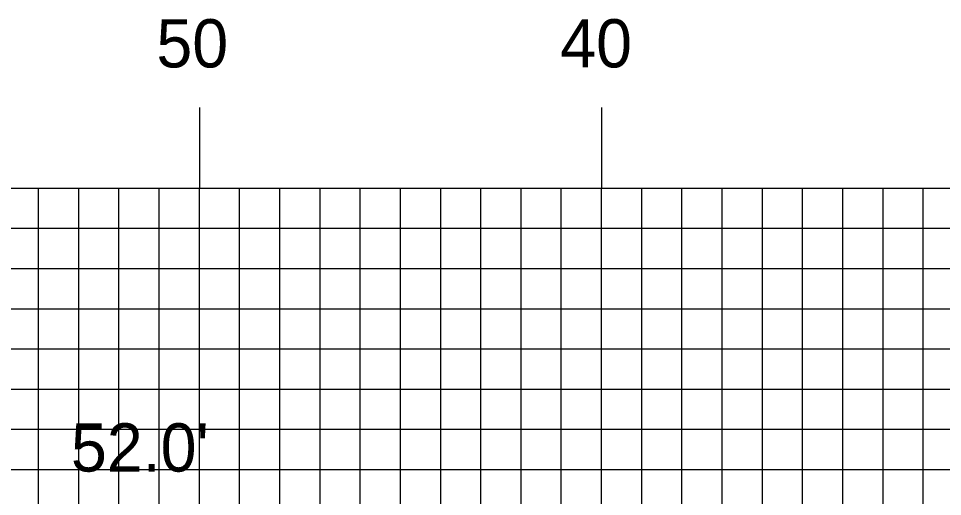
# Model space of a CAD drawing. Extents: x 1771629 to 1771972, y 442591 to 442811.
# Drawn here: x 1771740.08 to 1771763.06, y 442625.99 to 442637.88 of the extents above; entities that cross this region are included whole.
import ezdxf

# ---------------------------------------------------------------- set-up
doc = ezdxf.new("R2010")
doc.units = 0
for name, color, linetype in [('D_Text_Standard', 7, 'Continuous'), ('H_V ANNOTATION', 7, 'Continuous'), ('MAJOR', 7, 'Continuous'), ('MINOR', 7, 'Continuous')]:
    doc.layers.add(name, color=color, linetype=linetype)

msp = doc.modelspace()

# ---------------------------------------------------------------- linework, layer by layer
at = {"layer": 'MAJOR'}
for p, q in [((1771744.58, 442635.669), (1771744.58, 442633.665)), ((1771754.58, 442635.669), (1771754.58, 442633.665)), ((1771654.58, 442633.665), (1771934.58, 442633.665)), ((1771654.58, 442633.665), (1771934.58, 442633.665)), ((1771744.58, 442608.665), (1771744.58, 442633.665)), ((1771754.58, 442608.665), (1771754.58, 442633.665)), ((1771654.58, 442628.665), (1771934.58, 442628.665))]:
    msp.add_line(p, q, dxfattribs=at)
at = {"layer": 'MINOR'}
for p, q in [((1771740.58, 442608.665), (1771740.58, 442633.665)), ((1771741.58, 442608.665), (1771741.58, 442633.665)), ((1771742.58, 442608.665), (1771742.58, 442633.665)), ((1771743.58, 442608.665), (1771743.58, 442633.665)), ((1771745.58, 442608.665), (1771745.58, 442633.665)), ((1771746.58, 442608.665), (1771746.58, 442633.665)), ((1771747.58, 442608.665), (1771747.58, 442633.665)), ((1771748.58, 442608.665), (1771748.58, 442633.665)), ((1771749.58, 442608.665), (1771749.58, 442633.665)), ((1771750.58, 442608.665), (1771750.58, 442633.665)), ((1771751.58, 442608.665), (1771751.58, 442633.665)), ((1771752.58, 442608.665), (1771752.58, 442633.665)), ((1771753.58, 442608.665), (1771753.58, 442633.665)), ((1771755.58, 442608.665), (1771755.58, 442633.665)), ((1771756.58, 442608.665), (1771756.58, 442633.665)), ((1771757.58, 442608.665), (1771757.58, 442633.665)), ((1771758.58, 442608.665), (1771758.58, 442633.665)), ((1771759.58, 442608.665), (1771759.58, 442633.665)), ((1771760.58, 442608.665), (1771760.58, 442633.665)), ((1771761.58, 442608.665), (1771761.58, 442633.665)), ((1771762.58, 442608.665), (1771762.58, 442633.665)), ((1771654.58, 442632.665), (1771934.58, 442632.665)), ((1771654.58, 442631.665), (1771934.58, 442631.665)), ((1771654.58, 442630.665), (1771934.58, 442630.665)), ((1771654.58, 442629.665), (1771934.58, 442629.665)), ((1771654.58, 442627.665), (1771934.58, 442627.665)), ((1771654.58, 442626.665), (1771934.58, 442626.665))]:
    msp.add_line(p, q, dxfattribs=at)

# ---------------------------------------------------------------- texts
at = {"layer": 'D_Text_Standard'}
msp.add_text("52.0'", height=1.2, dxfattribs=at).set_placement((1771741.385, 442626.614))
at = {"layer": 'H_V ANNOTATION'}
for s, p in [('50', (1771743.51, 442636.665)), ('40', (1771753.553, 442636.665))]:
    msp.add_text(s, height=1.2, dxfattribs=at).set_placement(p)

doc.saveas('drawing.dxf')
